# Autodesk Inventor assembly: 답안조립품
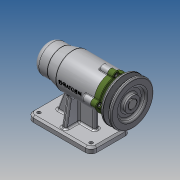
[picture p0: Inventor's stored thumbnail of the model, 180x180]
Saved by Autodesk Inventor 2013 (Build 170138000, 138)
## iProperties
Created: 2019-07
Part Number: 답안조립품
Document SubType Name: Assembly
Designer: Administrator
Author: Administrator
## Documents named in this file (12)
- C:\Users\Administrator\Desktop\490704V1081\답안조립품.iam
- C:\Users\Administrator\Desktop\490704V1081\본체.ipt
- C:\Users\Administrator\Desktop\490704V1081\V벨트풀리.ipt
- C:\Users\Administrator\Desktop\490704V1081\멈춤나사 M3.ipt
- C:\Users\Administrator\Desktop\490704V1081\베어링 6004.ipt
- C:\Users\Administrator\Desktop\490704V1081\베어링 51202.ipt
- C:\Users\Administrator\Desktop\490704V1081\볼트 M4.ipt
- C:\Users\Administrator\Desktop\490704V1081\어댑터슬리브.ipt
- C:\Users\Administrator\Desktop\490704V1081\오일 실.ipt
- C:\Users\Administrator\Desktop\490704V1081\축.ipt
- C:\Users\Administrator\Desktop\490704V1081\커버.ipt
- C:\Users\Administrator\Desktop\490704V1081\키 5 x 5 x 16.ipt
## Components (1 placed, 1 different names)
1. V벨트풀리:1
